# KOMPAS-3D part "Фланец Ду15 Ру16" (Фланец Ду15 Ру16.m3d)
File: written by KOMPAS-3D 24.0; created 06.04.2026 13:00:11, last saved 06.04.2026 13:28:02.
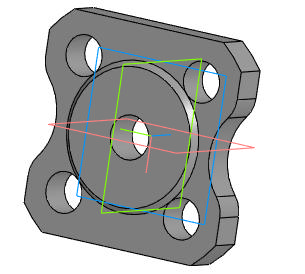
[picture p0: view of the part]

Document properties: Автор: R2D2; Полное имя файла: E:\Работа\Зайцев\Солянка\VSR1-13V-PED-F Клапан запорно-регулирующий DN.ru\DN15\DN15 Kv0.16\исходные материалы\Фланец Ду15 Ру16.m3d

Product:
- Component [standard]: Фланец квадратный 15-16-01-1-B-Ст 20-II-dв 19 ГОСТ 33259-2015  | qty 1  | Материал: Сталь 20 ГОСТ 1050-2013 (density 7859 kg/m3); Масса: 0.61; source file: C:\Program Files\ASCON\KOMPAS-3D v24\Libs\PolynomLib\DATA\vault\Methods\Kompas\3D\PLib_Flange_GOST_33259_1401.m3d
- Part/product: Фланец Ду15 Ру16
    Масса: 0.61

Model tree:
1. Эскиз:1
2. Элемент выдавливания:1
3. Скругление:1  (with: Ребро.Элемент выдавливания:1)
     Радиус = 10
4. Зеркальный массив:1
5. Экземпляр ( 1 )
6. Экземпляр ( 2 )  (with: Элемент выдавливания:1, Скругление:1)
7. Эскиз:2
8. Элемент выдавливания:2
     Расстояние 1 = -14

Expressions: v108*2
Referenced files in C:\Program Files\ASCON\KOMPAS-3D v24\Libs\PolynomLib\DATA\vault\Methods\Kompas\3D\: PLib_Flange_GOST_33259_1401.m3d
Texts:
  BOSimple***Material:399cd892-2a93-4364-bf9d-3db1a16b3f75
  BOSimple***PART:084cfe1f-7af2-896a-6270-73de92ccb36f***SHORTLOC:B6A6_23E38AE8DB154823[II;1;Квадратный;15;16;19;0;Сталь 20 ГОСТ 1050-2013]
  Ch34
  Плоскость XY.Начало координат
  Ось Z.Начало координат
  Плоскость ZY.Начало координат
